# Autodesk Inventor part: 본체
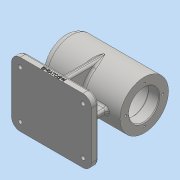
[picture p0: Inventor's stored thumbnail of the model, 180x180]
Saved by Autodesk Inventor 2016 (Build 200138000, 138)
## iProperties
Created: 2020-10
Part Number: 본체
Material: Generic
Document SubType Name: Modeling
Designer: User
Density: 1 g/cm^3
Appearance: Default
Mass: 380.103 g
Surface Area: 757.984 cm^2
Volume: 380.103 cm^3
Author: User
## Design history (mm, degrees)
sketch "스케치1"
  geometry: L1 (0, 0)-(132.063, 0); L2 (0, 0)-(0, 34); L3 (0, 34)-(112, 34); L4 (112, 34)-(112, 0); L5 (112, 21)-(97, 21); L6 (97, 21)-(97, 24); L7 (97, 24)-(43, 24); L8 (43, 24)-(43, 21); L9 (43, 21)-(31, 21); L10 (31, 21)-(31, 17.5); L11 (31, 17.5)-(13, 17.5); L12 (13, 17.5)-(13, 16); L13 (13, 16)-(9, 16); L14 (9, 16)-(9, 10.5); L15 (9, 10.5)-(6, 10.5); L16 (6, 10.5)-(6, 0)
  constraints: 32 end point, 12 perpendicular, 3 point on line, 2 horizontal, 1 vertical
  dimensions: "d0" = 112 distance of L2.end L3.end; "d1" = 68 diameter of L3 L1; "d2" = 48 diameter of L7 L1; "d3" = 42 diameter of L5 L1; "d5" = 42 diameter of L9 L1; "d8" = 32 diameter of L13 L1; "d9" = 35 diameter of L11 L1; "d10" = 21 diameter of L15 L1; "d11" = 15 distance of L5.start L5.end; "d12" = 54 distance of L6.end L7.end; "d13" = 12 distance of L8.end L9.end; "d14" = 18 distance of L10.end L11.end; "d15" = 4 distance of L12.end L13.end; "d16" = 3 distance of L14.end L15.end
revolve "회전1" sketch "스케치1" stored, may be unused: angle "d17" = 90 deg
fillet "모깎기1" dims "d18" = 3
chamfer "모따기1" distance "d19" = 1; stored, may be unused: second distance "d20" = 2, angle "d21" = 45 deg
fillet "모깎기2" dims "d22" = 0.3
node "작업 평면1"
sketch "스케치2"
  geometry: L1 (0, -45)-(-112, -45); L2 (-112, -45)-(-112, 45); L3 (-112, 45)-(0, 45); L4 (0, 45)-(0, -45); 2 further points
  constraints: 8 end point, 2 parallel, 1 coincident, 1 horizontal, 1 midpoint, 1 perpendicular
  dimensions: "d24" = 112 distance of L1.start L1.end; "d25" = 90 distance of L1.end L2.end
extrude "돌출1" join sketch "스케치2" distance "d26" = 10; taper "d27" = 0 deg
fillet "모깎기3" dims "d28" = 10
fillet "모깎기4" dims "d29" = 12
fillet "모깎기5" dims "d30" = 3
sketch "스케치3"
  geometry: L1 (0, 33)-(0, -33) reference; L2 (112, -33)-(112, 33) reference; L3 (18, 4)-(94, 4); L4 (94, 4)-(94, -4); L5 (94, -4)-(18, -4); L6 (18, -4)-(18, 4); 3 further points
  constraints: 8 end point, 2 midpoint, 2 parallel, 1 horizontal, 1 horizontal alignment, 1 perpendicular
  dimensions: "d31" = 18 distance between parallel lines of L2 L4; "d32" = 18 distance between parallel lines of L1 L6; "d33" = 8 distance of L3.end L4.end
extrude "돌출2" join sketch "스케치3" stored distance "d34" = 10; taper "d35" = 0 deg
sketch "스케치4"
  geometry: L1 (52, 34)-(60, 34); L2 (60, 34)-(60, -34); L3 (60, -34)-(52, -34); L4 (52, -34)-(52, 34); L5 (0, 33)-(0, -33) reference; L6 (100, 45)-(12, 45) reference; L7 (12, -45)-(100, -45) reference; L8 (56, 34)-(56, -34); L9 (112, -33)-(112, 33) reference; 3 further points
  constraints: 10 end point, 4 midpoint, 2 parallel, 1 horizontal, 1 horizontal alignment, 1 perpendicular
  dimensions: "d36" = 8 distance of L1.start L1.end; "d37" = 68 distance of L1.end L2.end; "d38" = 56 distance between parallel lines of L9 L8
extrude "돌출3" join sketch "스케치4" stored distance "d39" = 10; taper "d40" = 0 deg
fillet "모깎기6" dims "d41" = 3
fillet "모깎기7" dims "d42" = 3
fillet "모깎기8" dims "d43" = 3
fillet "모깎기9" dims "d44" = 3
sketch "스케치5"
  geometry: L1 (-12, 6)-(100, 6); L2 (100, 6)-(100, 0); L3 (100, 0)-(-12, 0); L4 (-12, 0)-(-12, 6); L5 (44, 6)-(44, 0); L6 (44, 3)-(100, 3); L7 (100, 0)-(100, 7) reference; L8 (88, 0)-(0, 0) reference; 1 further point
  constraints: 4 end point, 4 midpoint, 2 collinear, 2 other
  dimensions: "d46" = 3 vertical distance of L2.end L6.start; "d67" = 56 horizontal distance of L2.end L6.start
feature "엠보싱1" sketch "스케치5" dims "d0" = 112, "d1" = 68, "d2" = 48, "d3" = 42, "d5" = 42, "d8" = 32, "d9" = 35, "d10" = 21, "d11" = 15, "d12" = 54, "d13" = 12, "d14" = 18, "d15" = 4, "d16" = 3, "d47" = 0.5, "d48" = 0
sketch "스케치6" dims "d49" = 52
  geometry: L1 (0, 0)-(0, 26); 2 further points
  constraints: 2 coincident, 2 end point, 1 vertical, 1 vertical alignment, 2 other
hole "구멍1" sketch "스케치6" at (0, 26) diameter "d50" = 3.242; stored, may be unused: countersink angle "d54" = 90 deg, drill point angle "d56" = 118 deg; dims "d51" = 8, "d52" = 4, "d53" = 2, "d55" = 11
sketch "스케치7"
  geometry: A1 r 12 centre (12, 33) between (12, 45) and (0, 33) reference; A2 r 12 centre (12, -33) between (0, -33) and (12, -45) reference; A3 r 12 centre (100, -33) between (100, -45) and (112, -33) reference; A4 r 12 centre (100, 33) between (112, 33) and (100, 45) reference; 1 further point
hole "구멍2" sketch "스케치7" at (12, -33), (100, -33), (12, 33), (100, 33) diameter "d60" = 5.5; stored, may be unused: countersink angle "d64" = 90 deg, drill point angle "d66" = 118 deg; dims "d61" = 8, "d62" = 9.5, "d63" = 5.4, "d65" = 11
node "솔리드1"
pattern_circular "원형 패턴1" dims angle "d58" = 360 deg
other parameters: "d23" = -74
